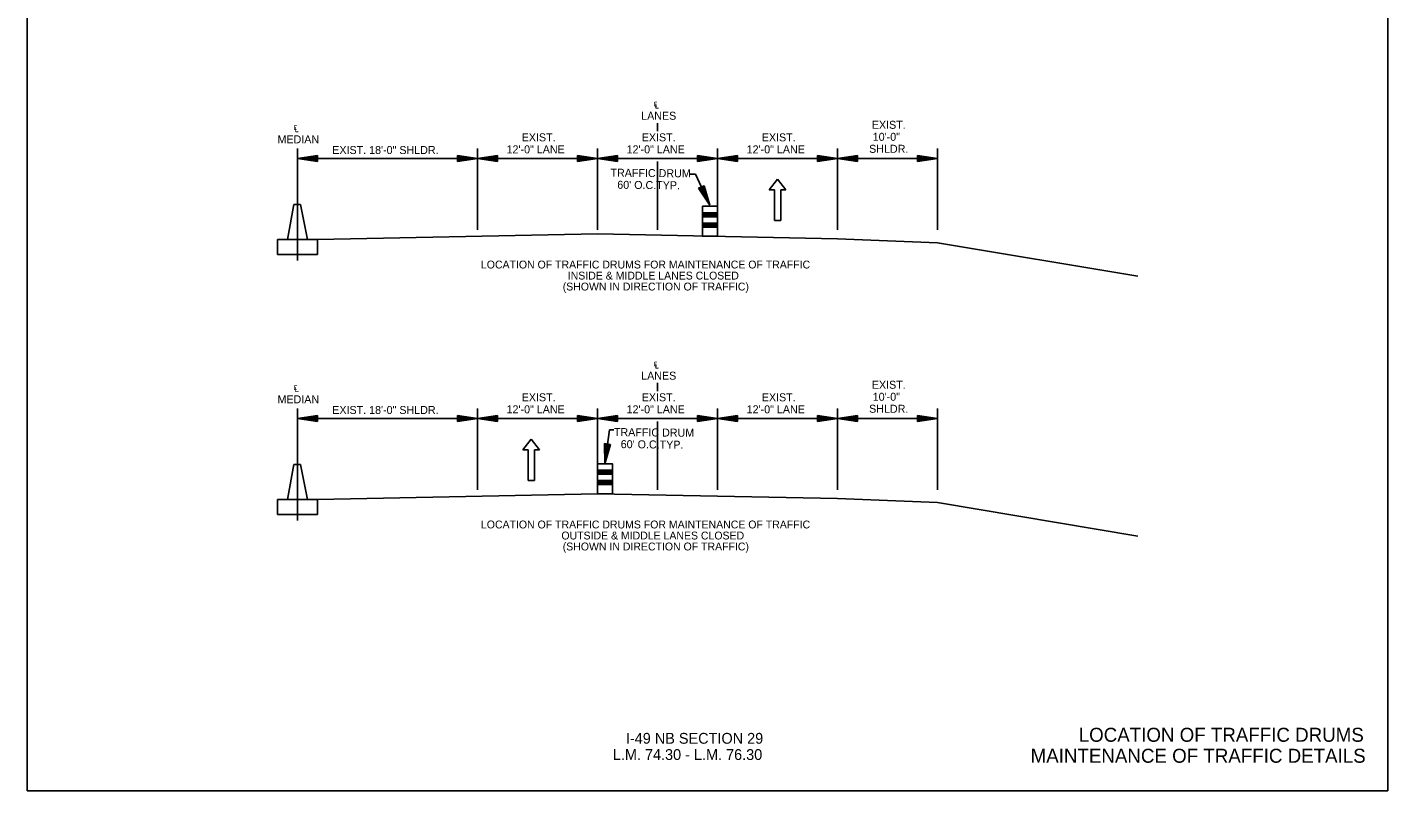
# Model space of a CAD drawing. Extents: x -100 to 745, y -1581 to -107.
# Drawn here: x 175.4 to 345.4, y -1580.6 to -1485.2 of the extents above; entities that cross this region are included whole.
import ezdxf

# ---------------------------------------------------------------- set-up
doc = ezdxf.new("R2010")
doc.units = 0
for name, color, linetype in [('Default', 7, 'Continuous'), ('R_Contour Annot', 7, 'Continuous'), ('R_Draft', 7, 'Continuous'), ('R_MOT', 7, 'Continuous')]:
    doc.layers.add(name, color=color, linetype=linetype)

msp = doc.modelspace()

# ---------------------------------------------------------------- linework, layer by layer
at = {"layer": 'Default'}
for p, q in [((254.16, -1497.15), (254.16, -1498.16)), ((209.16, -1500.34), (209.16, -1514.34)), ((231.66, -1500.34), (231.66, -1510.5)), ((246.66, -1500.34), (246.66, -1510.5)), ((261.66, -1500.34), (261.66, -1510.5)), ((276.66, -1500.34), (276.66, -1510.5)), ((289.16, -1500.34), (289.16, -1510.5)), ((211.66, -1501.22), (209.16, -1501.59)), ((231.66, -1501.59), (209.16, -1501.59)), ((211.66, -1501.97), (209.16, -1501.59)), ((211.66, -1501.28), (209.57, -1501.59)), ((211.66, -1501.9), (209.57, -1501.59)), ((211.66, -1501.34), (210, -1501.59)), ((211.66, -1501.84), (210, -1501.59)), ((211.66, -1501.4), (210.42, -1501.59)), ((211.66, -1501.78), (210.42, -1501.59)), ((211.66, -1501.47), (210.84, -1501.59)), ((211.66, -1501.71), (210.84, -1501.59)), ((211.66, -1501.53), (211.26, -1501.59)), ((211.66, -1501.65), (211.26, -1501.59)), ((211.66, -1501.22), (211.66, -1501.97)), ((229.16, -1501.22), (231.66, -1501.59)), ((229.16, -1501.22), (229.16, -1501.97)), ((229.16, -1501.28), (231.24, -1501.59)), ((229.16, -1501.34), (230.81, -1501.59)), ((229.16, -1501.4), (230.39, -1501.59)), ((229.16, -1501.47), (229.97, -1501.59)), ((229.16, -1501.53), (229.55, -1501.59)), ((229.16, -1501.97), (231.66, -1501.59)), ((229.16, -1501.71), (229.97, -1501.59)), ((229.16, -1501.84), (230.81, -1501.59)), ((229.16, -1501.9), (231.24, -1501.59)), ((229.16, -1501.78), (230.39, -1501.59)), ((229.16, -1501.65), (229.55, -1501.59)), ((234.16, -1501.22), (231.66, -1501.59)), ((231.66, -1501.59), (246.66, -1501.59)), ((234.16, -1501.97), (231.66, -1501.59)), ((234.16, -1501.28), (232.07, -1501.59)), ((234.16, -1501.9), (232.07, -1501.59)), ((234.16, -1501.34), (232.5, -1501.59)), ((234.16, -1501.84), (232.5, -1501.59)), ((234.16, -1501.4), (232.92, -1501.59)), ((234.16, -1501.78), (232.92, -1501.59)), ((234.16, -1501.47), (233.34, -1501.59)), ((234.16, -1501.71), (233.34, -1501.59)), ((234.16, -1501.53), (233.76, -1501.59)), ((234.16, -1501.65), (233.76, -1501.59)), ((234.16, -1501.22), (234.16, -1501.97)), ((244.16, -1501.22), (246.66, -1501.59)), ((244.16, -1501.22), (244.16, -1501.97)), ((244.16, -1501.28), (246.24, -1501.59)), ((244.16, -1501.34), (245.81, -1501.59)), ((244.16, -1501.4), (245.39, -1501.59)), ((244.16, -1501.47), (244.97, -1501.59)), ((244.16, -1501.53), (244.55, -1501.59)), ((244.16, -1501.97), (246.66, -1501.59)), ((244.16, -1501.71), (244.97, -1501.59)), ((244.16, -1501.84), (245.81, -1501.59)), ((244.16, -1501.9), (246.24, -1501.59)), ((244.16, -1501.78), (245.39, -1501.59)), ((244.16, -1501.65), (244.55, -1501.59)), ((249.16, -1501.22), (246.66, -1501.59)), ((246.66, -1501.59), (261.66, -1501.59)), ((249.16, -1501.97), (246.66, -1501.59)), ((249.16, -1501.28), (247.07, -1501.59)), ((249.16, -1501.9), (247.07, -1501.59)), ((249.16, -1501.34), (247.5, -1501.59)), ((249.16, -1501.84), (247.5, -1501.59)), ((249.16, -1501.4), (247.92, -1501.59)), ((249.16, -1501.78), (247.92, -1501.59)), ((249.16, -1501.47), (248.34, -1501.59)), ((249.16, -1501.71), (248.34, -1501.59)), ((249.16, -1501.53), (248.76, -1501.59)), ((249.16, -1501.65), (248.76, -1501.59)), ((249.16, -1501.22), (249.16, -1501.97)), ((254.16, -1501.97), (254.16, -1510.5)), ((259.16, -1501.22), (261.66, -1501.59)), ((259.16, -1501.22), (259.16, -1501.97)), ((259.16, -1501.28), (261.24, -1501.59)), ((259.16, -1501.34), (260.81, -1501.59)), ((259.16, -1501.4), (260.39, -1501.59)), ((259.16, -1501.47), (259.97, -1501.59)), ((259.16, -1501.53), (259.55, -1501.59)), ((259.16, -1501.97), (261.66, -1501.59)), ((259.16, -1501.71), (259.97, -1501.59)), ((259.16, -1501.84), (260.81, -1501.59)), ((259.16, -1501.9), (261.24, -1501.59)), ((259.16, -1501.78), (260.39, -1501.59)), ((259.16, -1501.65), (259.55, -1501.59)), ((264.16, -1501.22), (261.66, -1501.59)), ((261.66, -1501.59), (276.66, -1501.59)), ((264.16, -1501.97), (261.66, -1501.59)), ((264.16, -1501.28), (262.07, -1501.59)), ((264.16, -1501.9), (262.07, -1501.59)), ((264.16, -1501.34), (262.5, -1501.59)), ((264.16, -1501.84), (262.5, -1501.59)), ((264.16, -1501.4), (262.92, -1501.59)), ((264.16, -1501.78), (262.92, -1501.59)), ((264.16, -1501.47), (263.34, -1501.59)), ((264.16, -1501.71), (263.34, -1501.59)), ((264.16, -1501.53), (263.76, -1501.59)), ((264.16, -1501.65), (263.76, -1501.59)), ((264.16, -1501.22), (264.16, -1501.97)), ((274.16, -1501.22), (276.66, -1501.59)), ((274.16, -1501.22), (274.16, -1501.97)), ((274.16, -1501.28), (276.24, -1501.59)), ((274.16, -1501.34), (275.81, -1501.59)), ((274.16, -1501.4), (275.39, -1501.59)), ((274.16, -1501.47), (274.97, -1501.59)), ((274.16, -1501.53), (274.55, -1501.59)), ((274.16, -1501.97), (276.66, -1501.59)), ((274.16, -1501.71), (274.97, -1501.59)), ((274.16, -1501.84), (275.81, -1501.59)), ((274.16, -1501.9), (276.24, -1501.59)), ((274.16, -1501.78), (275.39, -1501.59)), ((274.16, -1501.65), (274.55, -1501.59)), ((279.16, -1501.22), (276.66, -1501.59)), ((276.66, -1501.59), (289.16, -1501.59)), ((279.16, -1501.97), (276.66, -1501.59)), ((279.16, -1501.28), (277.07, -1501.59)), ((279.16, -1501.9), (277.07, -1501.59)), ((279.16, -1501.34), (277.5, -1501.59)), ((279.16, -1501.84), (277.5, -1501.59)), ((279.16, -1501.4), (277.92, -1501.59)), ((279.16, -1501.78), (277.92, -1501.59)), ((279.16, -1501.47), (278.34, -1501.59)), ((279.16, -1501.71), (278.34, -1501.59)), ((279.16, -1501.53), (278.76, -1501.59)), ((279.16, -1501.65), (278.76, -1501.59)), ((279.16, -1501.22), (279.16, -1501.97)), ((286.66, -1501.22), (289.16, -1501.59)), ((286.66, -1501.22), (286.66, -1501.97)), ((286.66, -1501.28), (288.74, -1501.59)), ((286.66, -1501.34), (288.31, -1501.59)), ((286.66, -1501.4), (287.89, -1501.59)), ((286.66, -1501.47), (287.47, -1501.59)), ((286.66, -1501.53), (287.05, -1501.59)), ((286.66, -1501.97), (289.16, -1501.59)), ((286.66, -1501.71), (287.47, -1501.59)), ((286.66, -1501.84), (288.31, -1501.59)), ((286.66, -1501.9), (288.74, -1501.59)), ((286.66, -1501.78), (287.89, -1501.59)), ((286.66, -1501.65), (287.05, -1501.59)), ((258.91, -1503.53), (258.12, -1503.53)), ((260.68, -1507.42), (258.91, -1503.53)), ((268.11, -1505.5), (269.16, -1504.15)), ((269.16, -1504.15), (270.2, -1505.5)), ((259.99, -1504.99), (259.3, -1505.3)), ((259.3, -1505.3), (260.68, -1507.42)), ((259.36, -1505.27), (260.51, -1507.04)), ((259.42, -1505.25), (260.33, -1506.65)), ((259.48, -1505.22), (260.16, -1506.27)), ((259.53, -1505.19), (259.98, -1505.88)), ((259.59, -1505.17), (259.81, -1505.5)), ((259.7, -1505.12), (259.81, -1505.5)), ((259.76, -1505.09), (259.98, -1505.88)), ((259.82, -1505.07), (260.16, -1506.27)), ((259.87, -1505.04), (260.33, -1506.65)), ((259.93, -1505.01), (260.51, -1507.04)), ((259.99, -1504.99), (260.68, -1507.42)), ((268.11, -1505.5), (268.77, -1505.5)), ((268.77, -1505.5), (268.77, -1509.33)), ((269.55, -1505.5), (269.55, -1509.33)), ((269.55, -1505.5), (270.2, -1505.5)), ((208.74, -1507.33), (207.91, -1511.7)), ((209.16, -1507.33), (208.74, -1507.33)), ((209.16, -1507.33), (209.57, -1507.33)), ((209.57, -1507.33), (210.41, -1511.7)), ((259.78, -1508.35), (261.66, -1508.35)), ((259.78, -1508.42), (261.66, -1508.42)), ((259.78, -1508.49), (261.66, -1508.49)), ((259.78, -1508.55), (261.66, -1508.55)), ((259.78, -1508.63), (261.66, -1508.63)), ((259.78, -1508.72), (261.66, -1508.72)), ((259.78, -1508.81), (261.66, -1508.81)), ((259.78, -1508.86), (261.66, -1508.86)), ((268.77, -1509.33), (269.55, -1509.33)), ((246.66, -1511), (211.66, -1511.7)), ((246.66, -1511), (276.66, -1511.6)), ((259.78, -1509.64), (261.66, -1509.64)), ((259.78, -1509.71), (261.66, -1509.71)), ((259.78, -1509.78), (261.66, -1509.78)), ((259.78, -1509.84), (261.66, -1509.84)), ((259.78, -1509.91), (261.66, -1509.91)), ((259.78, -1510.01), (261.66, -1510.01)), ((259.78, -1510.09), (261.66, -1510.09)), ((259.78, -1510.14), (261.66, -1510.14)), ((206.66, -1511.7), (206.66, -1513.58)), ((209.16, -1511.7), (206.66, -1511.7)), ((209.16, -1511.7), (211.66, -1511.7)), ((211.66, -1511.7), (211.66, -1513.58)), ((276.66, -1511.6), (289.16, -1512.1)), ((289.16, -1512.1), (314.16, -1516.27)), ((206.66, -1513.58), (211.66, -1513.58)), ((254.16, -1529.63), (254.16, -1530.64)), ((209.16, -1532.82), (209.16, -1546.82)), ((231.66, -1532.82), (231.66, -1542.98)), ((246.66, -1532.82), (246.66, -1542.98)), ((261.66, -1532.82), (261.66, -1542.98)), ((276.66, -1532.82), (276.66, -1542.98)), ((289.16, -1532.82), (289.16, -1542.98)), ((211.66, -1533.7), (209.16, -1534.07)), ((231.66, -1534.07), (209.16, -1534.07)), ((211.66, -1534.45), (209.16, -1534.07)), ((211.66, -1533.76), (209.57, -1534.07)), ((211.66, -1534.39), (209.57, -1534.07)), ((211.66, -1533.82), (210, -1534.07)), ((211.66, -1534.32), (210, -1534.07)), ((211.66, -1533.89), (210.42, -1534.07)), ((211.66, -1534.26), (210.42, -1534.07)), ((211.66, -1533.95), (210.84, -1534.07)), ((211.66, -1534.2), (210.84, -1534.07)), ((211.66, -1534.01), (211.26, -1534.07)), ((211.66, -1534.13), (211.26, -1534.07)), ((211.66, -1533.7), (211.66, -1534.45)), ((229.16, -1533.7), (231.66, -1534.07)), ((229.16, -1533.7), (229.16, -1534.45)), ((229.16, -1533.76), (231.24, -1534.07)), ((229.16, -1533.82), (230.81, -1534.07)), ((229.16, -1533.89), (230.39, -1534.07)), ((229.16, -1533.95), (229.97, -1534.07)), ((229.16, -1534.01), (229.55, -1534.07)), ((229.16, -1534.45), (231.66, -1534.07)), ((229.16, -1534.2), (229.97, -1534.07)), ((229.16, -1534.32), (230.81, -1534.07)), ((229.16, -1534.39), (231.24, -1534.07)), ((229.16, -1534.26), (230.39, -1534.07)), ((229.16, -1534.13), (229.55, -1534.07)), ((234.16, -1533.7), (231.66, -1534.07)), ((231.66, -1534.07), (246.66, -1534.07)), ((234.16, -1534.45), (231.66, -1534.07)), ((234.16, -1533.76), (232.07, -1534.07)), ((234.16, -1534.39), (232.07, -1534.07)), ((234.16, -1533.82), (232.5, -1534.07)), ((234.16, -1534.32), (232.5, -1534.07)), ((234.16, -1533.89), (232.92, -1534.07)), ((234.16, -1534.26), (232.92, -1534.07)), ((234.16, -1533.95), (233.34, -1534.07)), ((234.16, -1534.2), (233.34, -1534.07)), ((234.16, -1534.01), (233.76, -1534.07)), ((234.16, -1534.13), (233.76, -1534.07)), ((234.16, -1533.7), (234.16, -1534.45)), ((244.16, -1533.7), (246.66, -1534.07)), ((244.16, -1533.7), (244.16, -1534.45)), ((244.16, -1533.76), (246.24, -1534.07)), ((244.16, -1533.82), (245.81, -1534.07)), ((244.16, -1533.89), (245.39, -1534.07)), ((244.16, -1533.95), (244.97, -1534.07)), ((244.16, -1534.01), (244.55, -1534.07)), ((244.16, -1534.45), (246.66, -1534.07)), ((244.16, -1534.2), (244.97, -1534.07)), ((244.16, -1534.32), (245.81, -1534.07)), ((244.16, -1534.39), (246.24, -1534.07)), ((244.16, -1534.26), (245.39, -1534.07)), ((244.16, -1534.13), (244.55, -1534.07)), ((249.16, -1533.7), (246.66, -1534.07)), ((246.66, -1534.07), (261.66, -1534.07)), ((249.16, -1534.45), (246.66, -1534.07)), ((249.16, -1533.76), (247.07, -1534.07)), ((249.16, -1534.39), (247.07, -1534.07)), ((249.16, -1533.82), (247.5, -1534.07)), ((249.16, -1534.32), (247.5, -1534.07)), ((249.16, -1533.89), (247.92, -1534.07)), ((249.16, -1534.26), (247.92, -1534.07)), ((249.16, -1533.95), (248.34, -1534.07)), ((249.16, -1534.2), (248.34, -1534.07)), ((249.16, -1534.01), (248.76, -1534.07)), ((249.16, -1534.13), (248.76, -1534.07)), ((249.16, -1533.7), (249.16, -1534.45)), ((254.16, -1534.45), (254.16, -1542.98)), ((259.16, -1533.7), (261.66, -1534.07)), ((259.16, -1533.7), (259.16, -1534.45)), ((259.16, -1533.76), (261.24, -1534.07)), ((259.16, -1533.82), (260.81, -1534.07)), ((259.16, -1533.89), (260.39, -1534.07)), ((259.16, -1533.95), (259.97, -1534.07)), ((259.16, -1534.01), (259.55, -1534.07)), ((259.16, -1534.45), (261.66, -1534.07)), ((259.16, -1534.2), (259.97, -1534.07)), ((259.16, -1534.32), (260.81, -1534.07)), ((259.16, -1534.39), (261.24, -1534.07)), ((259.16, -1534.26), (260.39, -1534.07)), ((259.16, -1534.13), (259.55, -1534.07)), ((264.16, -1533.7), (261.66, -1534.07)), ((261.66, -1534.07), (276.66, -1534.07)), ((264.16, -1534.45), (261.66, -1534.07)), ((264.16, -1533.76), (262.07, -1534.07)), ((264.16, -1534.39), (262.07, -1534.07)), ((264.16, -1533.82), (262.5, -1534.07)), ((264.16, -1534.32), (262.5, -1534.07)), ((264.16, -1533.89), (262.92, -1534.07)), ((264.16, -1534.26), (262.92, -1534.07)), ((264.16, -1533.95), (263.34, -1534.07)), ((264.16, -1534.2), (263.34, -1534.07)), ((264.16, -1534.01), (263.76, -1534.07)), ((264.16, -1534.13), (263.76, -1534.07)), ((264.16, -1533.7), (264.16, -1534.45)), ((274.16, -1533.7), (276.66, -1534.07)), ((274.16, -1533.7), (274.16, -1534.45)), ((274.16, -1533.76), (276.24, -1534.07)), ((274.16, -1533.82), (275.81, -1534.07)), ((274.16, -1533.89), (275.39, -1534.07)), ((274.16, -1533.95), (274.97, -1534.07)), ((274.16, -1534.01), (274.55, -1534.07)), ((274.16, -1534.45), (276.66, -1534.07)), ((274.16, -1534.2), (274.97, -1534.07)), ((274.16, -1534.32), (275.81, -1534.07)), ((274.16, -1534.39), (276.24, -1534.07)), ((274.16, -1534.26), (275.39, -1534.07)), ((274.16, -1534.13), (274.55, -1534.07)), ((279.16, -1533.7), (276.66, -1534.07)), ((276.66, -1534.07), (289.16, -1534.07)), ((279.16, -1534.45), (276.66, -1534.07)), ((279.16, -1533.76), (277.07, -1534.07)), ((279.16, -1534.39), (277.07, -1534.07)), ((279.16, -1533.82), (277.5, -1534.07)), ((279.16, -1534.32), (277.5, -1534.07)), ((279.16, -1533.89), (277.92, -1534.07)), ((279.16, -1534.26), (277.92, -1534.07)), ((279.16, -1533.95), (278.34, -1534.07)), ((279.16, -1534.2), (278.34, -1534.07)), ((279.16, -1534.01), (278.76, -1534.07)), ((279.16, -1534.13), (278.76, -1534.07)), ((279.16, -1533.7), (279.16, -1534.45)), ((286.66, -1533.7), (289.16, -1534.07)), ((286.66, -1533.7), (286.66, -1534.45)), ((286.66, -1533.76), (288.74, -1534.07)), ((286.66, -1533.82), (288.31, -1534.07)), ((286.66, -1533.89), (287.89, -1534.07)), ((286.66, -1533.95), (287.47, -1534.07)), ((286.66, -1534.01), (287.05, -1534.07)), ((286.66, -1534.45), (289.16, -1534.07)), ((286.66, -1534.2), (287.47, -1534.07)), ((286.66, -1534.32), (288.31, -1534.07)), ((286.66, -1534.39), (288.74, -1534.07)), ((286.66, -1534.26), (287.89, -1534.07)), ((286.66, -1534.13), (287.05, -1534.07)), ((237.34, -1537.99), (238.38, -1536.63)), ((238.38, -1536.63), (239.42, -1537.99)), ((247.59, -1539.73), (248.15, -1535.5)), ((248.15, -1535.5), (248.71, -1535.5)), ((237.34, -1537.99), (237.99, -1537.99)), ((237.99, -1537.99), (237.99, -1541.82)), ((238.77, -1537.99), (238.77, -1541.82)), ((238.77, -1537.99), (239.42, -1537.99)), ((247.55, -1537.21), (247.59, -1539.73)), ((247.55, -1537.21), (248.29, -1537.3)), ((248.29, -1537.3), (247.59, -1539.73)), ((247.61, -1537.21), (247.65, -1539.32)), ((248.23, -1537.3), (247.65, -1539.32)), ((247.67, -1537.22), (247.7, -1538.89)), ((248.17, -1537.29), (247.7, -1538.89)), ((247.74, -1537.23), (247.76, -1538.48)), ((248.11, -1537.28), (247.76, -1538.48)), ((247.8, -1537.24), (247.81, -1538.06)), ((248.04, -1537.27), (247.81, -1538.06)), ((247.86, -1537.25), (247.87, -1537.65)), ((247.98, -1537.26), (247.87, -1537.65)), ((208.74, -1539.81), (207.91, -1544.18)), ((209.16, -1539.81), (208.74, -1539.81)), ((209.16, -1539.81), (209.57, -1539.81)), ((209.57, -1539.81), (210.41, -1544.18)), ((237.99, -1541.82), (238.77, -1541.82)), ((246.66, -1540.54), (248.53, -1540.54)), ((246.66, -1540.61), (248.53, -1540.61)), ((246.66, -1540.68), (248.53, -1540.68)), ((246.66, -1540.74), (248.53, -1540.74)), ((246.66, -1540.81), (248.53, -1540.81)), ((246.66, -1540.9), (248.53, -1540.9)), ((246.66, -1540.99), (248.53, -1540.99)), ((246.66, -1541.04), (248.53, -1541.04)), ((246.66, -1541.82), (248.53, -1541.82)), ((246.66, -1541.89), (248.53, -1541.89)), ((246.66, -1543.48), (211.66, -1544.18)), ((246.66, -1541.96), (248.53, -1541.96)), ((246.66, -1542.02), (248.53, -1542.02)), ((246.66, -1542.1), (248.53, -1542.1)), ((246.66, -1542.19), (248.53, -1542.19)), ((246.66, -1542.27), (248.53, -1542.27)), ((246.66, -1542.33), (248.53, -1542.33)), ((246.66, -1543.48), (276.66, -1544.08)), ((206.66, -1544.18), (206.66, -1546.06)), ((209.16, -1544.18), (206.66, -1544.18)), ((209.16, -1544.18), (211.66, -1544.18)), ((211.66, -1544.18), (211.66, -1546.06)), ((276.66, -1544.08), (289.16, -1544.58)), ((289.16, -1544.58), (314.16, -1548.75)), ((206.66, -1546.06), (211.66, -1546.06))]:
    msp.add_line(p, q, dxfattribs=at)
for points in [[(259.78, -1507.55), (261.66, -1507.55), (261.66, -1511.3), (259.78, -1511.3)], [(246.66, -1539.73), (248.53, -1539.73), (248.53, -1543.48), (246.66, -1543.48)]]:
    msp.add_lwpolyline(points, close=True, dxfattribs=at)
at = {"layer": 'R_Contour Annot'}
msp.add_lwpolyline([(175.41, -1470.58), (345.41, -1470.58), (345.41, -1580.58), (175.41, -1580.58)], close=True, dxfattribs=at)
at = {"layer": 'R_Draft'}
msp.add_lwpolyline([(175.41, -1470.58), (175.41, -1580.58), (345.41, -1580.58), (345.41, -1470.58)], close=True, dxfattribs=at)

# ---------------------------------------------------------------- texts
at = {"layer": 'Default'}
for s, height, p in [('LANES', 1, (252.12, -1496.74)), ('℄', 1, (253.64, -1495.24)), ('℄', 1, (208.64, -1498.19)), ('EXIST.', 1, (280.94, -1497.87)), ('MEDIAN', 1, (206.68, -1499.69)), ('EXIST.', 1, (237.19, -1499.44)), ('EXIST.', 1, (252.19, -1499.44)), ('EXIST.', 1, (267.19, -1499.44)), ('10\'-0"', 1, (281.05, -1499.37)), ('EXIST. 18\'-0" SHLDR.', 1, (213.52, -1501.02)), ('12\'-0" LANE', 1, (235.3, -1500.94)), ('12\'-0" LANE', 1, (250.3, -1500.94)), ('12\'-0" LANE', 1, (265.3, -1500.94)), ('SHLDR.', 1, (280.6, -1500.87)), ('LOCATION OF TRAFFIC DRUMS FOR MAINTENANCE OF TRAFFIC', 0.9817, (232.1, -1515.32)), ('INSIDE & MIDDLE LANES CLOSED', 0.9817, (242.95, -1516.7)), ('(SHOWN IN DIRECTION OF TRAFFIC)', 0.9817, (242.32, -1518.07)), ('LANES', 1, (252.12, -1529.22)), ('℄', 1, (253.64, -1527.72)), ('℄', 1, (208.64, -1530.67)), ('EXIST.', 1, (280.94, -1530.35)), ('MEDIAN', 1, (206.68, -1532.17)), ('EXIST.', 1, (237.19, -1531.92)), ('EXIST.', 1, (252.19, -1531.92)), ('EXIST.', 1, (267.19, -1531.92)), ('10\'-0"', 1, (281.05, -1531.85)), ('EXIST. 18\'-0" SHLDR.', 1, (213.52, -1533.5)), ('12\'-0" LANE', 1, (235.3, -1533.42)), ('12\'-0" LANE', 1, (250.3, -1533.42)), ('12\'-0" LANE', 1, (265.3, -1533.42)), ('SHLDR.', 1, (280.6, -1533.35)), ('LOCATION OF TRAFFIC DRUMS FOR MAINTENANCE OF TRAFFIC', 0.9817, (232.1, -1547.8)), ('OUTSIDE & MIDDLE LANES CLOSED', 0.9817, (242.15, -1549.18)), ('(SHOWN IN DIRECTION OF TRAFFIC)', 0.9817, (242.32, -1550.55)), ('I-49 NB SECTION 29', 1.35, (250.21, -1574.7)), ('L.M. 74.30 - L.M. 76.30', 1.35, (248.58, -1576.73))]:
    msp.add_text(s, height=height, dxfattribs=at).set_placement(p)
for s, p in [('TRAFFIC DRUM ', (248.28, -1503.85)), ("60' O.C.TYP.", (249.13, -1505.36)), ('TRAFFIC DRUM ', (248.71, -1536.26)), ("60' O.C.TYP.", (249.56, -1537.77))]:
    msp.add_text(s, height=1, rotation=359.4561, dxfattribs=at).set_placement(p)
at = {"layer": 'R_MOT'}
for s, p in [('LOCATION OF TRAFFIC DRUMS', (306.79, -1574.46)), ('MAINTENANCE OF TRAFFIC DETAILS', (300.78, -1577.08))]:
    msp.add_text(s, height=1.75, dxfattribs=at).set_placement(p)

doc.saveas('drawing.dxf')
